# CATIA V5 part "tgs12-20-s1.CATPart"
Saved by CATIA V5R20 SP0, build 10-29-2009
Part number: TGS12-20-S1
Revision: 1
Definition: design
Nomenclature: TGS12-20-S1
Source: made
Description: NOT SPECIFIED
Bounding box of the stored display mesh (mm): x -22 to 0.8, y 0 to 12, z -5 to 5
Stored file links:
  C:\Users\Raffaele\Desktop\3D X SITO CF\I-MOLD\TGS-S1\tgs12-s1.step\tgs12-20-s1.CATPart
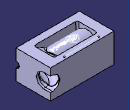
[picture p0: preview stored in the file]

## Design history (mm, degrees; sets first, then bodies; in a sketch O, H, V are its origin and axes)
Set1
  Line1 "LINE #3925": stored without definition
  DatumCurve1 "COMPOSITE_CURVE #3980"
  DatumCurve2 "COMPOSITE_CURVE #4029"
  DatumCurve3 "COMPOSITE_CURVE #4108"
  DatumCurve4 "COMPOSITE_CURVE #4151"
  DatumCurve5 "COMPOSITE_CURVE #4380"
  DatumCurve6 "COMPOSITE_CURVE #4521"
  DatumCurve7 "COMPOSITE_CURVE #4548"
  DatumCurve8 "COMPOSITE_CURVE #4606"
  DatumCurve9 "COMPOSITE_CURVE #4663"
  DatumCurve10 "COMPOSITE_CURVE #4692"
  DatumSurface1 "OPEN_SHELL #3915"
Body1 "MANIFOLD_SOLID_BREP #3916" (main body)
  Solid1: solid without history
